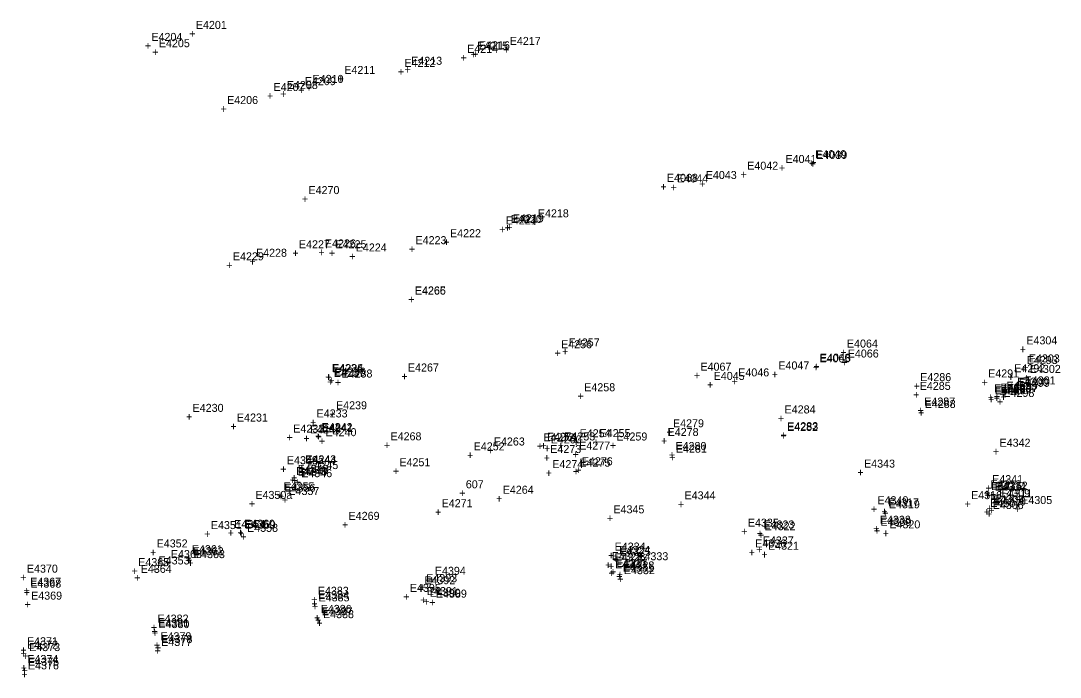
# Model space of a CAD drawing. Extents: x 1667192 to 1669644, y 336680 to 339991.
# Drawn here: x 1667201.2 to 1667525.8, y 336680.3 to 336885.1 of the extents above; entities that cross this region are included whole.
import ezdxf

# ---------------------------------------------------------------- set-up
doc = ezdxf.new("R2010")
doc.units = 0
for name, color, linetype in [('S_Bridge_ExpansionJoint', 7, 'Continuous'), ('S_Control_Temp_Traverse', 7, 'Continuous'), ('S_Curb_Type_1', 7, 'Continuous'), ('S_Curb_Type_3', 7, 'Continuous'), ('S_Curb_Type_5', 7, 'Continuous'), ('S_Drainage_CB', 7, 'Continuous'), ('S_Ground_Elevation', 7, 'Continuous'), ('S_Guardrail_Beam', 7, 'Continuous'), ('S_Misc_MiscFeature', 7, 'Continuous'), ('S_Roadway_Edge_Pavement', 7, 'Continuous'), ('S_Roadway_Edge_TW', 7, 'Continuous'), ('S_Roadway_Sidewalks', 7, 'Continuous'), ('S_Traffic_Sign_SinglePost', 7, 'Continuous'), ('S_Utilities_GuyWire3', 7, 'Continuous'), ('S_Utilities_Pole_Power', 7, 'Continuous'), ('S_Utilities_Pole_StreetLight', 7, 'Continuous'), ('S_Utilities_UG_Sanitary_MH', 7, 'Continuous')]:
    doc.layers.add(name, color=color, linetype=linetype)

msp = doc.modelspace()

# ---------------------------------------------------------------- texts
at = {"layer": 'S_Bridge_ExpansionJoint'}
for s, p in [('E4065', (1667450.57, 336778.55)), ('E4066', (1667459.43, 336780.07)), ('+', (1667448.51, 336775.8)), ('+', (1667457.37, 336777.32))]:
    msp.add_text(s, height=2.5, dxfattribs=at).set_placement(p)
at = {"layer": 'S_Control_Temp_Traverse'}
for s, p in [('607', (1667340.16, 336739.27)), ('607', (1667340.16, 336739.27)), ('607', (1667340.16, 336739.27)), ('+', (1667338.1, 336736.52)), ('+', (1667338.1, 336736.52)), ('+', (1667338.1, 336736.52))]:
    msp.add_text(s, height=2.5, dxfattribs=at).set_placement(p)
at = {"layer": 'S_Curb_Type_1'}
for s, p in [('E4237', (1667298.93, 336774)), ('+', (1667296.87, 336771.25)), ('E4242', (1667295.12, 336757.1)), ('+', (1667293.06, 336754.35)), ('E4243', (1667290.01, 336747.05)), ('E4248', (1667287.17, 336743.39)), ('+', (1667287.95, 336744.3)), ('+', (1667285.11, 336740.64)), ('E4355', (1667283.22, 336738.65)), ('+', (1667281.16, 336735.9)), ('E4360', (1667270.89, 336726.97)), ('+', (1667268.83, 336724.22)), ('E4366', (1667248.06, 336717.5)), ('E4361', (1667254.6, 336719.01)), ('+', (1667246, 336714.75)), ('+', (1667252.54, 336716.26))]:
    msp.add_text(s, height=2.5, dxfattribs=at).set_placement(p)
at = {"layer": 'S_Curb_Type_3'}
for s, p in [('E4367', (1667204.11, 336708.86)), ('+', (1667202.05, 336706.11))]:
    msp.add_text(s, height=2.5, dxfattribs=at).set_placement(p)
at = {"layer": 'S_Curb_Type_5'}
for s, p in [('E4216', (1667344.25, 336876.26)), ('+', (1667342.18, 336873.51)), ('E4219', (1667354.84, 336822.25)), ('+', (1667352.78, 336819.5)), ('E4300', (1667512.37, 336771.28)), ('E4290', (1667505.18, 336769.21)), ('E4294', (1667507.13, 336769.46)), ('E4295', (1667509, 336770.05)), ('+', (1667510.31, 336768.53)), ('E4287', (1667483.3, 336765.08)), ('+', (1667503.12, 336766.46)), ('+', (1667505.07, 336766.71)), ('+', (1667506.93, 336767.3)), ('+', (1667481.23, 336762.33)), ('E4283', (1667440.53, 336757.4)), ('E4260', (1667366.66, 336753.28)), ('+', (1667438.47, 336754.65)), ('+', (1667364.6, 336750.53)), ('E4280', (1667405.62, 336751.2)), ('E4276', (1667376.36, 336746.45)), ('+', (1667403.55, 336748.45)), ('+', (1667374.3, 336743.7)), ('E4315', (1667504.17, 336738.69)), ('E4314', (1667505.38, 336738.52)), ('E4309', (1667506.71, 336736.5)), ('E4319', (1667472.26, 336733.03)), ('+', (1667502.11, 336735.94)), ('+', (1667503.31, 336735.77)), ('+', (1667504.64, 336733.75)), ('E4308', (1667504.85, 336734.56)), ('+', (1667470.2, 336730.28)), ('+', (1667502.79, 336731.81)), ('E4322', (1667433.45, 336726.19)), ('E4338', (1667469.46, 336728.19)), ('+', (1667431.39, 336723.44)), ('+', (1667467.4, 336725.44)), ('E4337', (1667432.89, 336721.74)), ('E4326', (1667386.62, 336716.48)), ('E4325', (1667388.27, 336718.23)), ('+', (1667430.83, 336718.99)), ('+', (1667384.56, 336713.73)), ('+', (1667386.2, 336715.48)), ('E4327', (1667387.19, 336714.73)), ('E4328', (1667389.36, 336713.95)), ('+', (1667385.13, 336711.98)), ('+', (1667387.3, 336711.2))]:
    msp.add_text(s, height=2.5, dxfattribs=at).set_placement(p)
at = {"layer": 'S_Drainage_CB'}
for s, p in [('E4256', (1667369.91, 336782.96)), ('+', (1667367.85, 336780.21)), ('E4298', (1667508.05, 336767.78)), ('+', (1667505.99, 336765.03)), ('E4305', (1667513.6, 336734.35)), ('+', (1667511.54, 336731.6)), ('E4353', (1667244.22, 336715.51)), ('+', (1667242.16, 336712.76))]:
    msp.add_text(s, height=2.5, dxfattribs=at).set_placement(p)
at = {"layer": 'S_Ground_Elevation'}
for s, p in [('E4217', (1667353.88, 336877.6)), ('+', (1667351.82, 336874.85)), ('E4207', (1667280.13, 336863.22)), ('E4208', (1667284.26, 336863.84)), ('E4209', (1667289.89, 336865.05)), ('E4206', (1667265.61, 336859.16)), ('+', (1667278.07, 336860.47)), ('+', (1667282.2, 336861.09)), ('+', (1667287.83, 336862.3)), ('+', (1667263.55, 336856.41)), ('E4068', (1667402.97, 336834.89)), ('+', (1667400.91, 336832.14)), ('E4218', (1667362.65, 336823.82)), ('+', (1667360.59, 336821.07)), ('E4227', (1667288.05, 336814.16)), ('E4226', (1667296.16, 336814.43)), ('E4229', (1667267.42, 336810.39)), ('E4228', (1667274.64, 336811.51)), ('+', (1667285.99, 336811.41)), ('+', (1667294.1, 336811.68)), ('+', (1667265.36, 336807.64)), ('+', (1667272.58, 336808.76)), ('E4257', (1667372.28, 336783.52)), ('+', (1667370.22, 336780.77)), ('E4234', (1667298.34, 336775.54)), ('E4235', (1667298.48, 336775.44)), ('E4067', (1667413.43, 336775.97)), ('+', (1667296.28, 336772.79)), ('+', (1667296.42, 336772.69)), ('+', (1667411.37, 336773.22)), ('E4258', (1667377.14, 336769.55)), ('+', (1667375.08, 336766.8)), ('E4230', (1667254.84, 336763.11)), ('+', (1667252.78, 336760.36)), ('E4231', (1667268.69, 336760.1)), ('E4233', (1667293.57, 336761.38)), ('+', (1667266.63, 336757.35)), ('E4232', (1667286.27, 336756.64)), ('+', (1667291.51, 336758.63)), ('+', (1667284.2, 336753.89)), ('E4259', (1667387.18, 336754.18)), ('+', (1667385.12, 336751.43))]:
    msp.add_text(s, height=2.5, dxfattribs=at).set_placement(p)
at = {"layer": 'S_Guardrail_Beam'}
for s, p in [('E4039', (1667449.6, 336842.03)), ('+', (1667447.54, 336839.28)), ('E4044', (1667406.16, 336834.69)), ('+', (1667404.1, 336831.94)), ('E4064', (1667459.17, 336783.17)), ('+', (1667457.11, 336780.42)), ('E4045', (1667417.56, 336773.08)), ('+', (1667415.5, 336770.33))]:
    msp.add_text(s, height=2.5, dxfattribs=at).set_placement(p)
at = {"layer": 'S_Misc_MiscFeature'}
for s, p in [('E4392', (1667327.2, 336709.34)), ('E4385', (1667294.18, 336703.98)), ('+', (1667325.14, 336706.59)), ('E4391', (1667327.98, 336705.95)), ('+', (1667292.12, 336701.23)), ('E4386', (1667294.84, 336700.38)), ('+', (1667325.92, 336703.2)), ('+', (1667292.78, 336697.63)), ('E4380', (1667244.17, 336695.65)), ('+', (1667242.11, 336692.9)), ('E4379', (1667244.79, 336691.85)), ('E4373', (1667203.81, 336688.47)), ('+', (1667242.73, 336689.1)), ('+', (1667201.75, 336685.72)), ('E4374', (1667203.24, 336684.74)), ('+', (1667201.18, 336681.99))]:
    msp.add_text(s, height=2.5, dxfattribs=at).set_placement(p)
at = {"layer": 'S_Roadway_Edge_Pavement'}
for s, p in [('E4215', (1667343.67, 336876.12)), ('+', (1667341.61, 336873.37)), ('E4210', (1667292.31, 336865.75)), ('+', (1667290.25, 336863)), ('E4040', (1667449.28, 336842.27)), ('+', (1667447.22, 336839.52)), ('E4220', (1667354.25, 336822.07)), ('+', (1667352.19, 336819.32)), ('E4225', (1667299.47, 336814.17)), ('+', (1667297.4, 336811.42)), ('+', (1667513.14, 336781.42)), ('E4304', (1667515.2, 336784.17)), ('E4303', (1667515.97, 336778.54)), ('+', (1667513.91, 336775.79)), ('E4302', (1667516.28, 336775.27)), ('+', (1667297.16, 336771.65)), ('E4236', (1667299.22, 336774.4)), ('+', (1667514.22, 336772.52)), ('E4301', (1667514.68, 336771.69)), ('E4289', (1667505.3, 336768.57)), ('E4296', (1667507.08, 336768.93)), ('E4297', (1667509.14, 336769.3)), ('+', (1667512.62, 336768.94)), ('E4299', (1667512.86, 336770.93)), ('+', (1667503.24, 336765.82)), ('+', (1667505.02, 336766.18)), ('+', (1667507.08, 336766.55)), ('+', (1667510.8, 336768.18)), ('E4288', (1667483.45, 336764.34)), ('+', (1667481.39, 336761.59)), ('E4241', (1667295.28, 336756.88)), ('E4282', (1667440.47, 336757.16)), ('+', (1667293.22, 336754.13)), ('E4261', (1667365.52, 336754.1)), ('+', (1667438.41, 336754.41)), ('+', (1667363.46, 336751.35)), ('E4281', (1667405.76, 336750.39)), ('E4244', (1667290.08, 336746.93)), ('E4274', (1667367.17, 336745.56)), ('E4275', (1667375.64, 336746.03)), ('+', (1667403.7, 336747.64)), ('E4347', (1667287.7, 336743.25)), ('+', (1667288.01, 336744.18)), ('+', (1667365.11, 336742.81)), ('+', (1667373.58, 336743.28)), ('+', (1667285.64, 336740.5)), ('E4313', (1667504.02, 336739.27)), ('E4312', (1667505.92, 336738.85)), ('E4356', (1667283.53, 336738.21)), ('+', (1667501.96, 336736.52)), ('+', (1667503.86, 336736.1)), ('E4311', (1667507.39, 336736.43)), ('+', (1667281.47, 336735.46)), ('E4317', (1667471.99, 336733.6)), ('E4307', (1667503.94, 336733.42)), ('+', (1667505.33, 336733.68)), ('E4310', (1667505.35, 336733.95)), ('+', (1667469.93, 336730.85)), ('+', (1667501.88, 336730.67)), ('+', (1667503.29, 336731.2)), ('E4359', (1667271.1, 336726.67)), ('E4323', (1667433.08, 336726.72)), ('E4339', (1667469.65, 336727.56)), ('+', (1667269.04, 336723.92)), ('+', (1667431.02, 336723.97)), ('+', (1667467.59, 336724.81)), ('E4336', (1667430.55, 336720.81)), ('E4362', (1667254.85, 336718.39)), ('E4329', (1667385.71, 336716.85)), ('E4324', (1667388.08, 336718.81)), ('+', (1667428.49, 336718.06)), ('E4365', (1667237.86, 336714.98)), ('+', (1667252.79, 336715.64)), ('+', (1667383.64, 336714.1)), ('+', (1667386.02, 336716.06)), ('E4330', (1667386.76, 336714.33)), ('E4331', (1667389.19, 336713.27)), ('+', (1667235.8, 336712.23)), ('E4393', (1667327.78, 336709.96)), ('+', (1667384.7, 336711.58)), ('+', (1667387.13, 336710.52)), ('E4368', (1667204.16, 336708.28)), ('+', (1667325.72, 336707.21)), ('+', (1667202.1, 336705.53)), ('E4384', (1667294, 336704.74)), ('E4390', (1667328.89, 336705.43)), ('+', (1667291.94, 336701.99)), ('+', (1667326.83, 336702.68)), ('E4387', (1667295.15, 336699.65)), ('E4381', (1667244.11, 336696.14)), ('+', (1667293.09, 336696.9)), ('+', (1667242.05, 336693.39)), ('E4378', (1667245.11, 336691.01)), ('E4372', (1667203.16, 336689.2)), ('+', (1667243.05, 336688.26)), ('+', (1667201.09, 336686.45)), ('E4375', (1667203.46, 336683.91)), ('+', (1667201.4, 336681.16))]:
    msp.add_text(s, height=2.5, dxfattribs=at).set_placement(p)
at = {"layer": 'S_Roadway_Edge_TW'}
for s, p in [('E4214', (1667340.58, 336875.14)), ('+', (1667338.52, 336872.39)), ('E4212', (1667320.98, 336870.76)), ('E4213', (1667323.1, 336871.41)), ('+', (1667300.15, 336865.8)), ('E4211', (1667302.22, 336868.55)), ('+', (1667318.92, 336868.01)), ('+', (1667321.04, 336868.66)), ('E4041', (1667439.99, 336840.77)), ('E4042', (1667428.04, 336838.67)), ('+', (1667437.92, 336838.02)), ('E4043', (1667415.09, 336835.78)), ('+', (1667425.98, 336835.92)), ('+', (1667413.03, 336833.03)), ('E4221', (1667352.62, 336821.59)), ('E4222', (1667335.22, 336817.62)), ('+', (1667350.56, 336818.85)), ('E4223', (1667324.46, 336815.44)), ('+', (1667333.16, 336814.87)), ('E4224', (1667305.79, 336813.16)), ('+', (1667322.4, 336812.69)), ('+', (1667303.73, 336810.41)), ('E4266', (1667324.24, 336799.68)), ('E4265', (1667324.25, 336799.76)), ('+', (1667322.17, 336796.93)), ('+', (1667322.19, 336797.01)), ('E4048', (1667450.74, 336778.79)), ('E4267', (1667322.09, 336775.71)), ('E4047', (1667437.76, 336776.35)), ('+', (1667448.68, 336776.04)), ('E4238', (1667301.33, 336773.83)), ('+', (1667320.03, 336772.96)), ('E4046', (1667425.23, 336774.18)), ('+', (1667435.7, 336773.6)), ('+', (1667299.27, 336771.08)), ('+', (1667423.16, 336771.43)), ('E4239', (1667299.63, 336763.92)), ('+', (1667297.57, 336761.17)), ('E4240', (1667296.35, 336755.53)), ('+', (1667294.29, 336752.78)), ('E4268', (1667316.64, 336754.24)), ('E4263', (1667348.9, 336752.62)), ('E4272', (1667364.38, 336753.93)), ('E4342', (1667506.83, 336752.24)), ('+', (1667314.58, 336751.49)), ('+', (1667346.84, 336749.87)), ('+', (1667362.32, 336751.18)), ('+', (1667504.77, 336749.49)), ('E4245', (1667290.66, 336745.26)), ('E4343', (1667464.52, 336745.72)), ('+', (1667288.59, 336742.51)), ('E4346', (1667288.75, 336742.74)), ('+', (1667462.45, 336742.97)), ('+', (1667286.69, 336739.99)), ('E4341', (1667504.53, 336740.87)), ('E4357', (1667284.75, 336737.17)), ('E4264', (1667351.68, 336737.56)), ('E4344', (1667408.46, 336735.81)), ('+', (1667502.47, 336738.12)), ('+', (1667282.69, 336734.42)), ('E4271', (1667332.61, 336733.37)), ('+', (1667349.61, 336734.81)), ('+', (1667406.4, 336733.06)), ('E4340', (1667468.7, 336734.29)), ('E4306', (1667504.69, 336732.8)), ('E4269', (1667303.55, 336729.42)), ('+', (1667330.55, 336730.62)), ('E4345', (1667386.25, 336731.45)), ('+', (1667466.64, 336731.54)), ('+', (1667502.63, 336730.05)), ('+', (1667301.49, 336726.67)), ('+', (1667384.19, 336728.7)), ('E4335', (1667428.23, 336727.3)), ('E4320', (1667472.42, 336726.76)), ('E4358', (1667271.85, 336725.68)), ('+', (1667426.17, 336724.55)), ('+', (1667470.36, 336724.01)), ('+', (1667269.78, 336722.93)), ('E4334', (1667386.63, 336719.84)), ('E4321', (1667434.52, 336720.1)), ('E4363', (1667255.26, 336717.48)), ('+', (1667384.57, 336717.09)), ('+', (1667432.46, 336717.35)), ('E4364', (1667238.65, 336712.88)), ('+', (1667253.2, 336714.73)), ('+', (1667236.58, 336710.13)), ('E4394', (1667330.49, 336712.27)), ('E4332', (1667389.52, 336712.48)), ('+', (1667328.43, 336709.52)), ('+', (1667387.46, 336709.73)), ('E4369', (1667204.41, 336704.53)), ('E4383', (1667293.94, 336706.04)), ('E4389', (1667330.81, 336705.16)), ('+', (1667202.35, 336701.78)), ('+', (1667291.88, 336703.29)), ('+', (1667328.75, 336702.41)), ('E4382', (1667243.9, 336697.36)), ('E4388', (1667295.56, 336698.75)), ('+', (1667241.84, 336694.61)), ('+', (1667293.5, 336696)), ('E4371', (1667203.12, 336690.3)), ('E4377', (1667245, 336690.07)), ('+', (1667201.06, 336687.55)), ('+', (1667242.94, 336687.32)), ('E4376', (1667203.42, 336682.76)), ('+', (1667201.36, 336680.01))]:
    msp.add_text(s, height=2.5, dxfattribs=at).set_placement(p)
at = {"layer": 'S_Roadway_Sidewalks'}
for s, p in [('E4293', (1667515.32, 336778.03)), ('E4292', (1667511.43, 336775.49)), ('+', (1667513.26, 336775.28)), ('E4291', (1667503.27, 336773.86)), ('+', (1667509.37, 336772.74)), ('E4285', (1667481.9, 336769.97)), ('+', (1667501.2, 336771.11)), ('+', (1667479.84, 336767.22)), ('E4284', (1667439.7, 336762.63)), ('+', (1667437.64, 336759.88)), ('E4278', (1667403.18, 336755.59)), ('+', (1667401.12, 336752.84)), ('E4273', (1667366.53, 336750.28)), ('E4277', (1667375.56, 336751.33)), ('E4349', (1667284.28, 336746.76)), ('E4348a', (1667284.3, 336746.79)), ('+', (1667364.47, 336747.53)), ('+', (1667373.5, 336748.58)), ('+', (1667282.22, 336744.01)), ('+', (1667282.24, 336744.04)), ('E4348', (1667287.64, 336744.06)), ('+', (1667285.58, 336741.31)), ('E4350a', (1667274.45, 336735.95)), ('+', (1667272.39, 336733.2)), ('E4351', (1667260.54, 336726.54)), ('+', (1667258.48, 336723.8)), ('E4352', (1667243.61, 336720.82)), ('+', (1667241.54, 336718.07)), ('E4370', (1667203.09, 336712.95)), ('+', (1667201.03, 336710.2))]:
    msp.add_text(s, height=2.5, dxfattribs=at).set_placement(p)
at = {"layer": 'S_Traffic_Sign_SinglePost'}
for s, p in [('E4286', (1667482.07, 336772.7)), ('+', (1667480.01, 336769.95)), ('E4279', (1667404.86, 336758.3)), ('E4249', (1667291.49, 336756.37)), ('E4254', (1667375.7, 336755.19)), ('+', (1667402.79, 336755.55)), ('+', (1667289.43, 336753.62)), ('E4253', (1667370.91, 336754.2)), ('+', (1667373.64, 336752.44)), ('E4252', (1667342.61, 336751.1)), ('+', (1667368.85, 336751.45)), ('E4251', (1667319.42, 336746.15)), ('+', (1667340.54, 336748.35)), ('+', (1667317.36, 336743.4)), ('E4316', (1667497.94, 336735.89)), ('+', (1667495.88, 336733.14)), ('E4333', (1667393.72, 336716.82)), ('+', (1667391.66, 336714.07)), ('E4395', (1667322.68, 336706.95)), ('+', (1667320.62, 336704.2))]:
    msp.add_text(s, height=2.5, dxfattribs=at).set_placement(p)
at = {"layer": 'S_Utilities_GuyWire3'}
for s, p in [('E4204', (1667241.97, 336878.85)), ('+', (1667239.91, 336876.1)), ('E4205', (1667244.3, 336876.9)), ('+', (1667242.24, 336874.15))]:
    msp.add_text(s, height=2.5, dxfattribs=at).set_placement(p)
at = {"layer": 'S_Utilities_Pole_Power'}
for s, p in [('E4201', (1667255.85, 336882.6)), ('+', (1667253.79, 336879.85))]:
    msp.add_text(s, height=2.5, dxfattribs=at).set_placement(p)
at = {"layer": 'S_Utilities_Pole_StreetLight'}
for s, p in [('E4270', (1667291.02, 336831.06)), ('+', (1667288.96, 336828.31)), ('E4255', (1667381.92, 336755.23)), ('+', (1667379.86, 336752.48))]:
    msp.add_text(s, height=2.5, dxfattribs=at).set_placement(p)
at = {"layer": 'S_Utilities_UG_Sanitary_MH'}
for s, p in [('E4354', (1667267.85, 336726.87)), ('+', (1667265.79, 336724.12))]:
    msp.add_text(s, height=2.5, dxfattribs=at).set_placement(p)

doc.saveas('drawing.dxf')
